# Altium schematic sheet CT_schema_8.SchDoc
size 226 x 144 mm
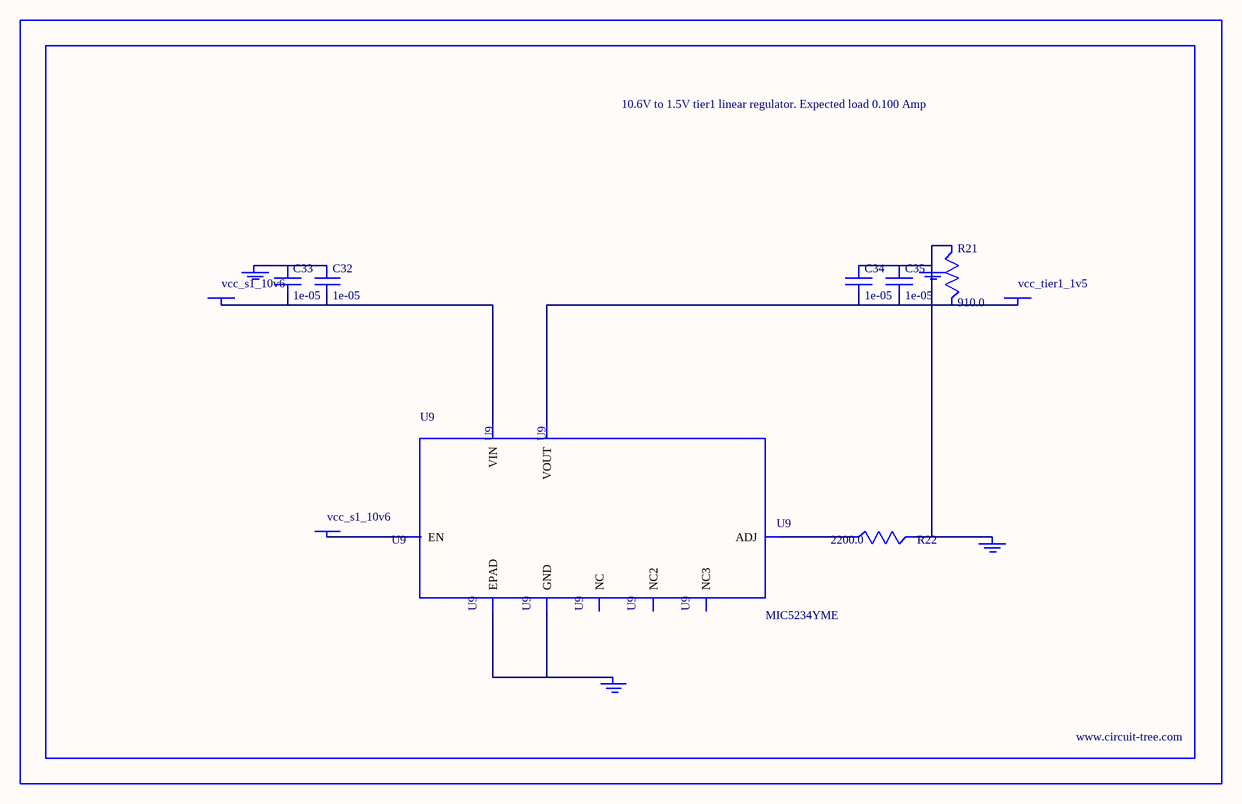
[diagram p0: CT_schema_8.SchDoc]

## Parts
BORDER7  (no value)
C32  1e-05  [C1210]
C33  1e-05  [C1210]
C34  1e-05  [C1210]
C35  1e-05  [C1210]
GND_INSTANCE_7_0  (no value)
GND_INSTANCE_7_1  (no value)
GND_INSTANCE_7_2  (no value)
GND_INSTANCE_7_3  (no value)
POWER_INSTANCE_7_0  vcc_tier1_1v5
POWER_INSTANCE_7_1  vcc_s1_10v6
POWER_INSTANCE_7_2  vcc_s1_10v6
R21  910.0  [R0603]
R22  2200.0  [R0603]
U9  MIC5234YME  [SOIC-8_EP]

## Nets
NetC32_1: C32.1 C33.1 GND_INSTANCE_7_3.0(GND)
NetC32_2: C32.2 C33.2 POWER_INSTANCE_7_2.0(PWR) U9.8(VIN)
NetC34_1: C34.1 C35.1 GND_INSTANCE_7_0.0(GND) GND_INSTANCE_7_1.0(GND) R21.1 R22.2
NetC34_2: C34.2 C35.2 POWER_INSTANCE_7_0.0(PWR) R21.2 U9.1(VOUT)
NetGND_INSTANCE_7_2_0: GND_INSTANCE_7_2.0(GND) U9.7(GND) U9.EPAD
NetPOWER_INSTANCE_7_1_0: POWER_INSTANCE_7_1.0(PWR) U9.5(EN)
NetR22_1: R22.1 U9.4(ADJ)

Not connected (* = marked no-connect by the designer): U9 2(NC) 3(NC2) 6(NC3)

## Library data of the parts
BORDER7 = BORDER_PAGE7
C32-C35 = C1210C106K5PACTU
GND_INSTANCE_7_0-GND_INSTANCE_7_3 = GND
POWER_INSTANCE_7_0-POWER_INSTANCE_7_2 = PWR
R21 = RC0603JR-07910RL
R22 = RC0603JR-072K2L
